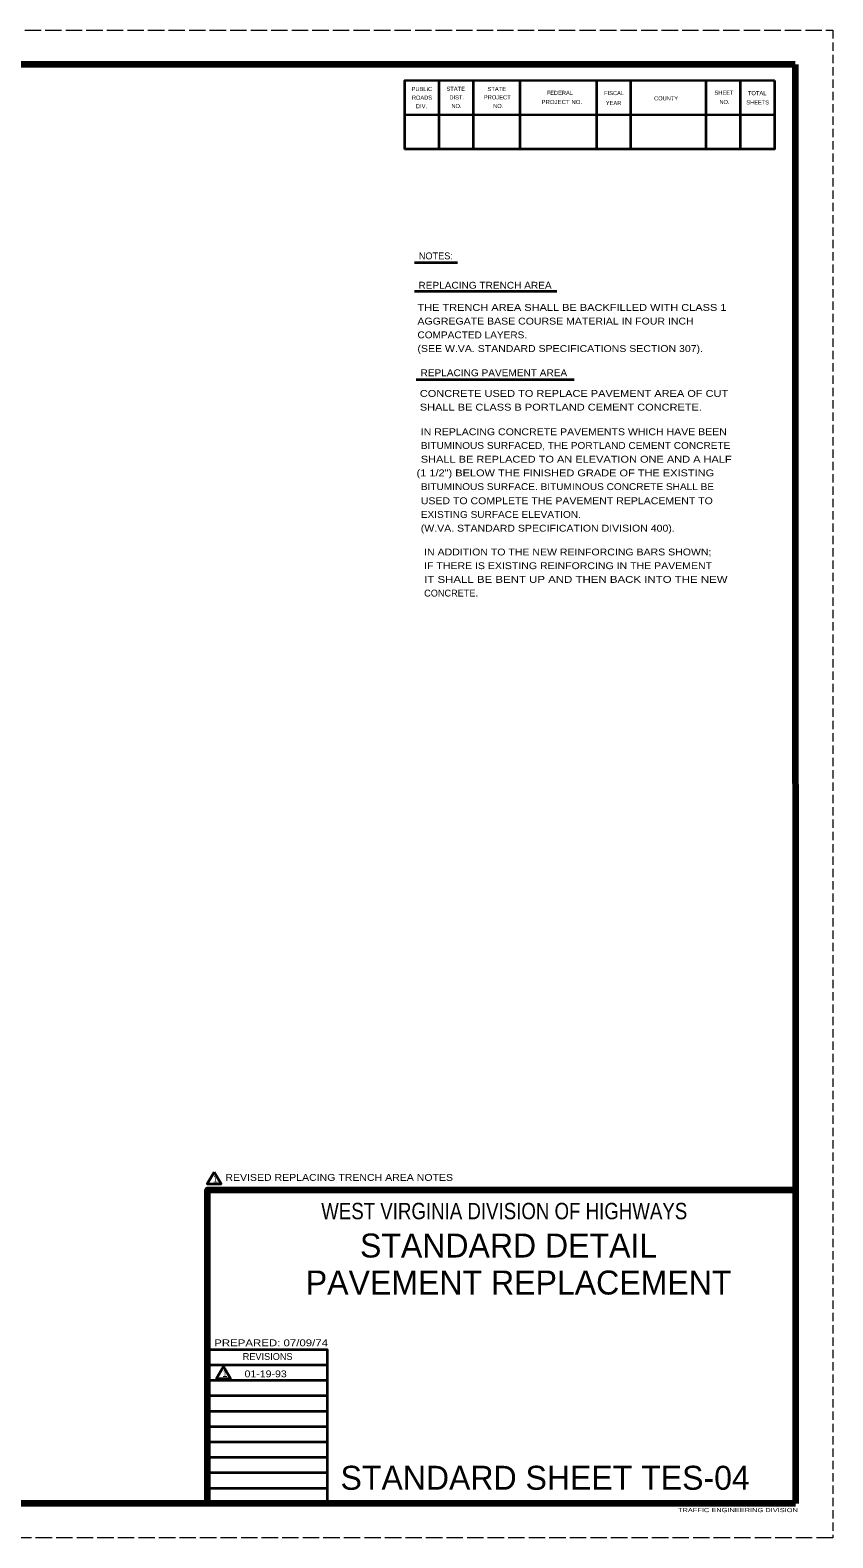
# Model space of a CAD drawing. Extents: x -488 to 193, y 19 to 459.
# Drawn here: x -41.9 to 192.5, y 18.9 to 458.9 of the extents above; entities that cross this region are included whole.
import ezdxf
from ezdxf.enums import TextEntityAlignment as Align

# ---------------------------------------------------------------- set-up
doc = ezdxf.new("R2010")
doc.units = 0
doc.header["$LTSCALE"] = 0.8
doc.linetypes.add('LONG_DASHED', pattern=[7.5, 6, -1.5])
doc.linetypes.add('MEDIUM_DASHED', pattern=[4.5, 3, -1.5])
doc.layers.add('1', color=7, linetype='Continuous', lineweight=40)
doc.layers.add('61', color=7, linetype='Continuous', lineweight=35)

msp = doc.modelspace()

# ---------------------------------------------------------------- linework, layer by layer
at = {"layer": '1', "linetype": 'MEDIUM_DASHED', "lineweight": 13}
msp.add_line((192.5172, 458.891), (192.4972, 18.871), dxfattribs=at)
at = {"layer": '1', "lineweight": 35}
for p, q in [((70.3632, 391.063), (82.8514, 391.063)), ((70.3632, 382.6848), (111.9381, 382.6848)), ((70.8375, 356.9182), (116.9964, 356.9182)), ((44.8972, 69.291), (9.9172, 69.291)), ((44.8972, 64.791), (9.9172, 64.791)), ((44.8972, 60.291), (9.9172, 60.291)), ((44.8972, 55.771), (9.9172, 55.771)), ((44.8972, 51.291), (9.9172, 51.291)), ((44.8972, 46.811), (9.9172, 46.811)), ((44.8972, 42.311), (9.9172, 42.311)), ((44.8972, 37.811), (9.9172, 37.811)), ((44.8972, 33.291), (9.9172, 33.291))]:
    msp.add_line(p, q, dxfattribs=at)
for points in [[(11.8347, 125.6181), (9.8347, 122.154), (13.8347, 122.154)], [(14.5628, 68.8358), (12.5628, 65.3717), (16.5628, 65.3717)]]:
    msp.add_lwpolyline(points, close=True, dxfattribs=at)
at = {"layer": '1', "lineweight": 158}
msp.add_lwpolyline([(9.8972, 28.851), (9.8972, 120.431), (181.5572, 120.431)], dxfattribs=at)
at = {"layer": '1', "lineweight": 35}
msp.add_lwpolyline([(44.8972, 28.811), (44.8972, 73.771), (9.9172, 73.771)], dxfattribs=at)
at = {"layer": '61', "linetype": 'LONG_DASHED', "lineweight": 13}
for p, q in [((-487.5027, 458.891), (192.5172, 458.891)), ((192.4972, 18.871), (-487.5627, 18.851))]:
    msp.add_line(p, q, dxfattribs=at)
at = {"layer": '61', "lineweight": 158}
for p, q in [((181.5373, 448.891), (181.5572, 28.851)), ((181.5572, 28.851), (-457.5027, 28.871))]:
    msp.add_line(p, q, dxfattribs=at)
at = {"layer": '61'}
for p, q in [((77.4573, 444.131), (77.4573, 424.131)), ((87.4573, 444.131), (87.4573, 424.131)), ((101.1372, 444.131), (101.1372, 424.131)), ((123.4573, 444.131), (123.4573, 424.131)), ((133.4572, 444.131), (133.4572, 424.131)), ((155.4373, 444.151), (155.4373, 424.151)), ((165.4373, 444.151), (165.4373, 424.151)), ((175.4572, 434.111), (67.4372, 434.131))]:
    msp.add_line(p, q, dxfattribs=at)
at = {"layer": '61', "lineweight": 158}
msp.add_lwpolyline([(181.5373, 448.891), (-457.5027, 448.891), (-457.5027, 28.871)], dxfattribs=at)
at = {"layer": '61'}
for points in [[(175.4373, 444.151), (67.4573, 444.131), (67.4573, 424.131)], [(175.4373, 444.151), (175.4373, 424.151), (67.4573, 424.131)]]:
    msp.add_lwpolyline(points, dxfattribs=at)

# ---------------------------------------------------------------- texts
at = {"layer": '1'}
for s, height, p in [('NOTES:', 2, (71.5991, 392.0113)), ('CONCRETE.', 2, (73.1559, 293.5839)), ('REVISIONS', 1.998, (20.1773, 70.771)), ('STANDARD SHEET TES-04', 6.993, (48.7372, 32.891))]:
    msp.add_text(s, height=height, dxfattribs=at).set_placement(p)
for s, height, width, p in [('REPLACING TRENCH AREA', 2, 1.1, (71.4843, 383.4393)), ('THE TRENCH AREA SHALL BE BACKFILLED WITH CLASS 1', 2, 1.2, (71.1997, 376.9614)), ('AGGREGATE BASE COURSE MATERIAL IN FOUR INCH', 2, 1.15, (71.1997, 372.9614)), ('COMPACTED LAYERS.', 2, 1.1, (71.1997, 368.9614)), ('(SEE W.VA. STANDARD SPECIFICATIONS SECTION 307).', 2, 1.15, (71.1997, 364.9614)), ('REPLACING PAVEMENT AREA', 2, 1.1, (72.0977, 357.8888)), ('CONCRETE USED TO REPLACE PAVEMENT AREA OF CUT', 2, 1.2, (71.8932, 351.8561)), ('SHALL BE CLASS B PORTLAND CEMENT CONCRETE.', 2, 1.2, (71.8932, 347.8561)), ('IN REPLACING CONCRETE PAVEMENTS WHICH HAVE BEEN', 2, 1.15, (72.1779, 340.6683)), ('SHALL BE REPLACED TO AN ELEVATION ONE AND A HALF', 2, 1.2, (72.1779, 332.6683)), ('BITUMINOUS SURFACED, THE PORTLAND CEMENT CONCRETE', 2, 1.1, (72.1779, 336.6683)), (' (1 1/2") BELOW THE FINISHED GRADE OF THE EXISTING', 2, 1.2, (70.0434, 328.6684)), ('BITUMINOUS SURFACE. BITUMINOUS CONCRETE SHALL BE ', 2, 1.1, (72.1779, 324.6683)), ('USED TO COMPLETE THE PAVEMENT REPLACEMENT TO', 2, 1.15, (72.1778, 320.5317)), ('EXISTING SURFACE ELEVATION. ', 2, 1.1, (72.1778, 316.5317)), ('(W.VA. STANDARD SPECIFICATION DIVISION 400).', 2, 1.15, (72.1778, 312.5317)), ('IN ADDITION TO THE NEW REINFORCING BARS SHOWN; ', 2, 1.15, (73.1559, 305.5839)), ('IF THERE IS EXISTING REINFORCING IN THE PAVEMENT ', 2, 1.15, (73.1559, 301.5839)), ('IT SHALL BE BENT UP AND THEN BACK INTO THE NEW', 2, 1.25, (73.1559, 297.5839)), ('PREPARED: 07/09/74', 1.998, 1.25, (11.8572, 74.771)), ('TRAFFIC ENGINEERING DIVISION', 1.2, 1.35, (147.2772, 26.351))]:
    msp.add_text(s, height=height, dxfattribs=dict(at, width=width)).set_placement(p)
for s, height, p in [('1', 2, (12.2438, 122.6239)), ('STANDARD DETAIL', 6.993, (97.8142, 100.671)), ('PAVEMENT REPLACEMENT', 7, (100.7473, 89.8683)), ('1', 2, (14.9719, 65.8416))]:
    msp.add_text(s, height=height, dxfattribs=at).set_placement(p, align=Align.CENTER)
for s, height, width, p in [('REVISED REPLACING TRENCH AREA NOTES', 2, 1.15, (48.3484, 123.0438)), ('WEST VIRGINIA DIVISION OF HIGHWAYS', 4.795, 0.85, (96.5456, 111.831)), ('01-19-93', 2, 1.15, (26.8666, 65.711))]:
    msp.add_text(s, height=height, dxfattribs=dict(at, width=width)).set_placement(p, align=Align.CENTER)
at = {"layer": '61'}
for s, rotation, p in [('PUBLIC', 0.033, (69.4972, 441.111)), ('FEDERAL', 0.007, (108.9573, 439.991)), ('FISCAL', 359.942, (125.6972, 439.931)), ('SHEET', 0.059, (157.9572, 440.051)), ('ROADS', 0.124, (69.5772, 438.591)), ('DIV.', 359.932, (70.7772, 436.091)), ('DIST.', 0.056, (80.5373, 438.671)), ('YEAR', 0.105, (126.2172, 437.031)), ('COUNTY', 0.069, (140.3173, 438.391)), ('SHEETS', 359.959, (167.2372, 437.211))]:
    msp.add_text(s, height=1.201, rotation=rotation, dxfattribs=at).set_placement(p)
for s, rotation, width, p in [('STATE', 0.059, 1.05, (79.6572, 441.171)), ('STATE', 0.059, 1.05, (91.6572, 441.111)), ('TOTAL', 359.926, 1.05, (167.6972, 439.911)), ('NO.', 359.852, 0.95, (81.1172, 436.151)), ('PROJECT', 359.908, 1.05, (90.5772, 438.691)), ('NO.', 0.225, 0.95, (93.3173, 436.151)), ('PROJECT NO.', 359.922, 1.1, (107.4172, 437.331)), ('NO.', 359.852, 0.95, (159.3773, 437.331))]:
    msp.add_text(s, height=1.201, rotation=rotation, dxfattribs=dict(at, width=width)).set_placement(p)

doc.saveas('drawing.dxf')
